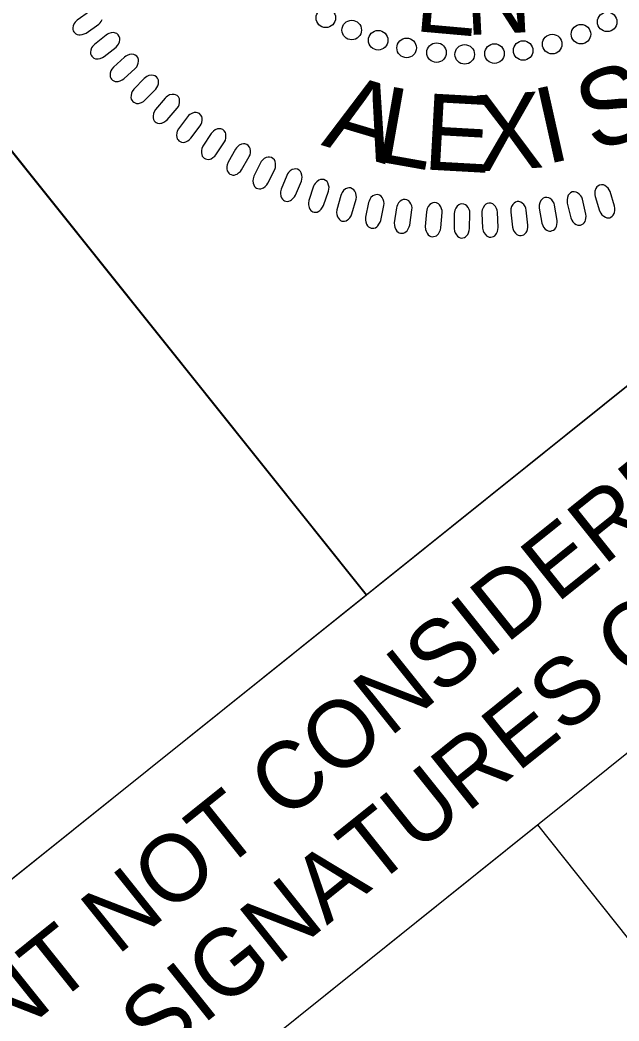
# Model space of a CAD drawing. Extents: x 472510 to 474509, y 505091 to 506998.
# Drawn here: x 473812.8 to 473861.9, y 506755.4 to 506837.4 of the extents above; entities that cross this region are included whole.
import ezdxf

# ---------------------------------------------------------------- set-up
doc = ezdxf.new("R2010")
doc.units = 0
for name, color, linetype in [('Sheet Clip Boundary CELL', 7, 'Continuous'), ('Sheet PE Seal Cell', 7, 'Continuous'), ('Sheet Plan CELL', 7, 'Continuous'), ('Sheet Sticker Exception Certification CELL', 7, 'Continuous'), ('Sheet Sticker Incomplete CELL', 7, 'Continuous')]:
    doc.layers.add(name, color=color, linetype=linetype)

msp = doc.modelspace()

# ---------------------------------------------------------------- linework, layer by layer
at = {"layer": 'Sheet Clip Boundary CELL'}
msp.add_lwpolyline([(473777.72, 506709.447), (473669.277, 506844.945), (472855.074, 506193.317), (472968.618, 506051.104), (472829.891, 505940.077), (472768.979, 505889.401), (473229.883, 505313.507), (473287.266, 505310.531), (473108.816, 505533.501), (473372.025, 505744.154), (473550.474, 505521.184), (474139.22, 505988.542), (474128.73, 506014.502), (474324.313, 506183.285), (473855.207, 506771.462)], close=True, dxfattribs=at)
at = {"layer": 'Sheet PE Seal Cell'}
msp.add_lwpolyline([(473818.447, 506838.07), (473817.443, 506837.365), (473817.284, 506837.208), (473817.2, 506837.085), (473817.125, 506836.896), (473817.091, 506836.753), (473817.091, 506836.616), (473817.118, 506836.507), (473817.166, 506836.404), (473817.247, 506836.324), (473817.341, 506836.243), (473817.449, 506836.192), (473817.591, 506836.163), (473817.691, 506836.16), (473817.852, 506836.191), (473818.033, 506836.245), (473818.177, 506836.318), (473819.21, 506837.034), (473819.336, 506837.15), (473819.424, 506837.267), (473819.503, 506837.432)], dxfattribs=at)
for points in [[(473819.814, 506836.153), (473818.856, 506835.386), (473818.709, 506835.22), (473818.632, 506835.092), (473818.569, 506834.899), (473818.544, 506834.754), (473818.553, 506834.617), (473818.587, 506834.511), (473818.641, 506834.41), (473818.727, 506834.336), (473818.825, 506834.261), (473818.936, 506834.216), (473819.08, 506834.197), (473819.18, 506834.2), (473819.339, 506834.241), (473819.516, 506834.306), (473819.655, 506834.388), (473820.641, 506835.168), (473820.759, 506835.29), (473820.84, 506835.413), (473820.908, 506835.583), (473820.948, 506835.757), (473820.949, 506835.883), (473820.898, 506836.043), (473820.82, 506836.173), (473820.695, 506836.264), (473820.591, 506836.314), (473820.434, 506836.352), (473820.227, 506836.339), (473820.045, 506836.28), (473819.925, 506836.222)], [(473821.329, 506834.345), (473820.42, 506833.52), (473820.283, 506833.345), (473820.215, 506833.212), (473820.165, 506833.015), (473820.148, 506832.869), (473820.165, 506832.733), (473820.206, 506832.629), (473820.267, 506832.532), (473820.357, 506832.463), (473820.46, 506832.395), (473820.574, 506832.357), (473820.718, 506832.347), (473820.818, 506832.356), (473820.973, 506832.407), (473821.147, 506832.483), (473821.279, 506832.574), (473822.215, 506833.413), (473822.325, 506833.544), (473822.398, 506833.671), (473822.456, 506833.845), (473822.484, 506834.022), (473822.478, 506834.147), (473822.417, 506834.304), (473822.331, 506834.428), (473822.201, 506834.512), (473822.093, 506834.556), (473821.934, 506834.582), (473821.729, 506834.557), (473821.55, 506834.486), (473821.434, 506834.421)], [(473822.945, 506832.589), (473822.09, 506831.709), (473821.965, 506831.525), (473821.904, 506831.389), (473821.867, 506831.189), (473821.86, 506831.042), (473821.885, 506830.907), (473821.933, 506830.806), (473821.999, 506830.713), (473822.093, 506830.649), (473822.2, 506830.587), (473822.317, 506830.557), (473822.462, 506830.556), (473822.56, 506830.572), (473822.712, 506830.632), (473822.88, 506830.719), (473823.007, 506830.818), (473823.888, 506831.715), (473823.99, 506831.852), (473824.055, 506831.984), (473824.102, 506832.16), (473824.119, 506832.338), (473824.105, 506832.463), (473824.034, 506832.616), (473823.94, 506832.734), (473823.805, 506832.81), (473823.695, 506832.847), (473823.535, 506832.864), (473823.331, 506832.825), (473823.158, 506832.743), (473823.046, 506832.671)], [(473824.658, 506830.981), (473823.861, 506830.049), (473823.746, 506829.858), (473823.695, 506829.719), (473823.67, 506829.516), (473823.673, 506829.37), (473823.706, 506829.236), (473823.76, 506829.138), (473823.832, 506829.05), (473823.93, 506828.993), (473824.04, 506828.938), (473824.159, 506828.915), (473824.303, 506828.923), (473824.4, 506828.944), (473824.549, 506829.014), (473824.711, 506829.112), (473824.832, 506829.218), (473825.654, 506830.168), (473825.747, 506830.312), (473825.804, 506830.447), (473825.84, 506830.626), (473825.845, 506830.806), (473825.823, 506830.929), (473825.743, 506831.077), (473825.642, 506831.19), (473825.503, 506831.256), (473825.391, 506831.287), (473825.23, 506831.293), (473825.029, 506831.242), (473824.86, 506831.149), (473824.754, 506831.07)], [(473826.495, 506829.453), (473825.758, 506828.473), (473825.656, 506828.275), (473825.613, 506828.132), (473825.601, 506827.929), (473825.613, 506827.783), (473825.655, 506827.652), (473825.715, 506827.557), (473825.792, 506827.474), (473825.894, 506827.423), (473826.007, 506827.375), (473826.127, 506827.359), (473826.271, 506827.376), (473826.367, 506827.404), (473826.51, 506827.483), (473826.666, 506827.591), (473826.779, 506827.705), (473827.541, 506828.704), (473827.625, 506828.853), (473827.673, 506828.992), (473827.697, 506829.173), (473827.691, 506829.352), (473827.662, 506829.474), (473827.572, 506829.617), (473827.464, 506829.723), (473827.321, 506829.78), (473827.207, 506829.803), (473827.046, 506829.801), (473826.849, 506829.736), (473826.687, 506829.634), (473826.585, 506829.548)], [(473828.433, 506828.079), (473827.759, 506827.054), (473827.669, 506826.85), (473827.635, 506826.705), (473827.636, 506826.501), (473827.658, 506826.356), (473827.707, 506826.228), (473827.773, 506826.137), (473827.855, 506826.059), (473827.96, 506826.015), (473828.076, 506825.974), (473828.196, 506825.966), (473828.339, 506825.992), (473828.433, 506826.025), (473828.571, 506826.113), (473828.72, 506826.231), (473828.826, 506826.351), (473829.523, 506827.397), (473829.597, 506827.551), (473829.637, 506827.692), (473829.649, 506827.875), (473829.633, 506828.053), (473829.596, 506828.173), (473829.497, 506828.309), (473829.383, 506828.408), (473829.236, 506828.457), (473829.122, 506828.473), (473828.961, 506828.46), (473828.768, 506828.384), (473828.613, 506828.271), (473828.517, 506828.179)], [(473830.423, 506826.806), (473829.814, 506825.741), (473829.738, 506825.532), (473829.714, 506825.385), (473829.727, 506825.182), (473829.757, 506825.038), (473829.815, 506824.913), (473829.886, 506824.827), (473829.973, 506824.754), (473830.08, 506824.716), (473830.199, 506824.683), (473830.319, 506824.682), (473830.46, 506824.717), (473830.552, 506824.757), (473830.685, 506824.853), (473830.825, 506824.98), (473830.924, 506825.107), (473831.554, 506826.194), (473831.619, 506826.353), (473831.649, 506826.496), (473831.65, 506826.679), (473831.622, 506826.856), (473831.578, 506826.973), (473831.471, 506827.103), (473831.351, 506827.195), (473831.202, 506827.234), (473831.086, 506827.243), (473830.926, 506827.22), (473830.738, 506827.131), (473830.59, 506827.009), (473830.501, 506826.911)], [(473832.475, 506825.683), (473831.934, 506824.581), (473831.871, 506824.368), (473831.856, 506824.219), (473831.883, 506824.018), (473831.921, 506823.876), (473831.987, 506823.755), (473832.063, 506823.673), (473832.155, 506823.606), (473832.264, 506823.575), (473832.385, 506823.549), (473832.505, 506823.556), (473832.643, 506823.6), (473832.732, 506823.645), (473832.859, 506823.75), (473832.991, 506823.885), (473833.082, 506824.018), (473833.643, 506825.142), (473833.697, 506825.305), (473833.718, 506825.45), (473833.708, 506825.632), (473833.669, 506825.807), (473833.617, 506825.922), (473833.502, 506826.045), (473833.376, 506826.129), (473833.225, 506826.158), (473833.109, 506826.16), (473832.951, 506826.127), (473832.77, 506826.027), (473832.629, 506825.895), (473832.545, 506825.792)], [(473834.635, 506824.659), (473834.165, 506823.526), (473834.115, 506823.31), (473834.11, 506823.16), (473834.148, 506822.961), (473834.196, 506822.822), (473834.269, 506822.706), (473834.35, 506822.628), (473834.447, 506822.567), (473834.557, 506822.543), (473834.68, 506822.525), (473834.799, 506822.539), (473834.934, 506822.592), (473835.02, 506822.642), (473835.139, 506822.755), (473835.263, 506822.898), (473835.346, 506823.036), (473835.834, 506824.194), (473835.878, 506824.359), (473835.89, 506824.505), (473835.868, 506824.687), (473835.819, 506824.858), (473835.76, 506824.97), (473835.637, 506825.085), (473835.507, 506825.161), (473835.353, 506825.181), (473835.238, 506825.176), (473835.082, 506825.132), (473834.907, 506825.021), (473834.776, 506824.881), (473834.699, 506824.773)], [(473836.834, 506823.762), (473836.436, 506822.601), (473836.4, 506822.382), (473836.404, 506822.233), (473836.455, 506822.036), (473836.511, 506821.901), (473836.592, 506821.789), (473836.678, 506821.717), (473836.777, 506821.662), (473836.89, 506821.645), (473837.013, 506821.634), (473837.131, 506821.656), (473837.262, 506821.717), (473837.345, 506821.773), (473837.457, 506821.893), (473837.572, 506822.043), (473837.645, 506822.186), (473838.06, 506823.373), (473838.094, 506823.54), (473838.096, 506823.687), (473838.064, 506823.867), (473838.003, 506824.035), (473837.937, 506824.143), (473837.808, 506824.25), (473837.673, 506824.317), (473837.519, 506824.328), (473837.404, 506824.315), (473837.251, 506824.262), (473837.083, 506824.14), (473836.96, 506823.992), (473836.891, 506823.879)], [(473839.065, 506823.018), (473838.74, 506821.834), (473838.718, 506821.613), (473838.731, 506821.464), (473838.795, 506821.271), (473838.86, 506821.14), (473838.947, 506821.033), (473839.037, 506820.967), (473839.14, 506820.918), (473839.253, 506820.908), (473839.377, 506820.905), (473839.494, 506820.935), (473839.621, 506821.004), (473839.699, 506821.065), (473839.804, 506821.191), (473839.909, 506821.348), (473839.973, 506821.496), (473840.313, 506822.706), (473840.336, 506822.875), (473840.329, 506823.022), (473840.285, 506823.199), (473840.214, 506823.363), (473840.142, 506823.467), (473840.006, 506823.566), (473839.867, 506823.625), (473839.712, 506823.625), (473839.598, 506823.605), (473839.449, 506823.543), (473839.289, 506823.411), (473839.177, 506823.255), (473839.114, 506823.139)], [(473859.922, 506822.926), (473860.282, 506821.753), (473860.382, 506821.554), (473860.472, 506821.436), (473860.63, 506821.306), (473860.755, 506821.23), (473860.886, 506821.187), (473860.997, 506821.179), (473861.111, 506821.193), (473861.211, 506821.245), (473861.317, 506821.309), (473861.4, 506821.396), (473861.47, 506821.523), (473861.504, 506821.616), (473861.524, 506821.779), (473861.529, 506821.968), (473861.504, 506822.128), (473861.142, 506823.331), (473861.072, 506823.487), (473860.987, 506823.606), (473860.855, 506823.733), (473860.707, 506823.834), (473860.59, 506823.881), (473860.423, 506823.893), (473860.273, 506823.868), (473860.143, 506823.786), (473860.058, 506823.707), (473859.965, 506823.575), (473859.901, 506823.378), (473859.889, 506823.186), (473859.899, 506823.054)], [(473841.337, 506822.426), (473841.087, 506821.224), (473841.079, 506821.003), (473841.101, 506820.855), (473841.176, 506820.666), (473841.249, 506820.539), (473841.343, 506820.438), (473841.437, 506820.378), (473841.543, 506820.335), (473841.656, 506820.332), (473841.78, 506820.337), (473841.894, 506820.374), (473842.017, 506820.451), (473842.092, 506820.517), (473842.189, 506820.65), (473842.283, 506820.813), (473842.338, 506820.964), (473842.601, 506822.194), (473842.614, 506822.364), (473842.598, 506822.51), (473842.543, 506822.684), (473842.462, 506822.844), (473842.383, 506822.942), (473842.241, 506823.032), (473842.099, 506823.082), (473841.945, 506823.073), (473841.832, 506823.046), (473841.687, 506822.974), (473841.535, 506822.833), (473841.432, 506822.67), (473841.377, 506822.549)], [(473843.622, 506821.987), (473843.448, 506820.772), (473843.454, 506820.55), (473843.485, 506820.405), (473843.572, 506820.22), (473843.653, 506820.098), (473843.753, 506820.003), (473843.851, 506819.949), (473843.959, 506819.914), (473844.073, 506819.918), (473844.196, 506819.93), (473844.307, 506819.974), (473844.425, 506820.059), (473844.496, 506820.129), (473844.584, 506820.268), (473844.668, 506820.437), (473844.713, 506820.591), (473844.899, 506821.834), (473844.901, 506822.005), (473844.875, 506822.15), (473844.81, 506822.32), (473844.719, 506822.475), (473844.634, 506822.567), (473844.487, 506822.649), (473844.341, 506822.69), (473844.188, 506822.671), (473844.077, 506822.637), (473843.937, 506822.556), (473843.795, 506822.405), (473843.703, 506822.237), (473843.655, 506822.113)], [(473852.997, 506821.649), (473853.131, 506820.429), (473853.191, 506820.215), (473853.258, 506820.082), (473853.388, 506819.925), (473853.497, 506819.827), (473853.617, 506819.76), (473853.725, 506819.731), (473853.839, 506819.724), (473853.948, 506819.756), (473854.064, 506819.798), (473854.161, 506819.87), (473854.255, 506819.98), (473854.306, 506820.066), (473854.356, 506820.222), (473854.396, 506820.407), (473854.401, 506820.568), (473854.271, 506821.818), (473854.23, 506821.984), (473854.171, 506822.118), (473854.064, 506822.267), (473853.938, 506822.394), (473853.832, 506822.462), (473853.67, 506822.505), (473853.519, 506822.508), (473853.375, 506822.452), (473853.276, 506822.391), (473853.16, 506822.279), (473853.06, 506822.097), (473853.013, 506821.911), (473852.997, 506821.779)], [(473855.332, 506821.96), (473855.542, 506820.752), (473855.616, 506820.542), (473855.691, 506820.413), (473855.831, 506820.265), (473855.945, 506820.174), (473856.07, 506820.114), (473856.179, 506820.093), (473856.294, 506820.093), (473856.4, 506820.132), (473856.513, 506820.181), (473856.606, 506820.258), (473856.692, 506820.375), (473856.737, 506820.463), (473856.778, 506820.622), (473856.806, 506820.809), (473856.801, 506820.97), (473856.593, 506822.21), (473856.542, 506822.373), (473856.473, 506822.503), (473856.358, 506822.645), (473856.224, 506822.763), (473856.115, 506822.825), (473855.95, 506822.857), (473855.799, 506822.851), (473855.659, 506822.786), (473855.564, 506822.719), (473855.456, 506822.599), (473855.367, 506822.412), (473855.331, 506822.223), (473855.324, 506822.091)], [(473857.631, 506822.383), (473857.916, 506821.191), (473858.004, 506820.986), (473858.087, 506820.862), (473858.236, 506820.723), (473858.356, 506820.639), (473858.483, 506820.588), (473858.594, 506820.573), (473858.708, 506820.58), (473858.812, 506820.626), (473858.922, 506820.682), (473859.009, 506820.765), (473859.088, 506820.886), (473859.128, 506820.978), (473859.159, 506821.139), (473859.175, 506821.327), (473859.16, 506821.488), (473858.875, 506822.712), (473858.813, 506822.872), (473858.737, 506822.996), (473858.613, 506823.131), (473858.471, 506823.241), (473858.358, 506823.296), (473858.192, 506823.317), (473858.041, 506823.302), (473857.905, 506823.229), (473857.815, 506823.155), (473857.715, 506823.029), (473857.638, 506822.837), (473857.615, 506822.646), (473857.616, 506822.513)], [(473846.088, 506821.683), (473845.991, 506820.46), (473846.01, 506820.238), (473846.051, 506820.095), (473846.15, 506819.917), (473846.238, 506819.799), (473846.343, 506819.711), (473846.444, 506819.664), (473846.555, 506819.635), (473846.668, 506819.646), (473846.79, 506819.666), (473846.899, 506819.717), (473847.011, 506819.809), (473847.077, 506819.883), (473847.156, 506820.027), (473847.229, 506820.201), (473847.265, 506820.359), (473847.372, 506821.611), (473847.363, 506821.781), (473847.329, 506821.924), (473847.252, 506822.09), (473847.152, 506822.238), (473847.061, 506822.325), (473846.91, 506822.398), (473846.761, 506822.43), (473846.61, 506822.401), (473846.501, 506822.36), (473846.367, 506822.271), (473846.234, 506822.111), (473846.153, 506821.937), (473846.113, 506821.811)], [(473848.363, 506821.544), (473848.343, 506820.317), (473848.377, 506820.097), (473848.426, 506819.957), (473848.536, 506819.786), (473848.632, 506819.674), (473848.742, 506819.593), (473848.846, 506819.551), (473848.958, 506819.529), (473849.07, 506819.547), (473849.19, 506819.575), (473849.296, 506819.633), (473849.402, 506819.732), (473849.464, 506819.81), (473849.533, 506819.959), (473849.596, 506820.137), (473849.621, 506820.296), (473849.649, 506821.553), (473849.63, 506821.723), (473849.586, 506821.863), (473849.5, 506822.024), (473849.391, 506822.165), (473849.294, 506822.247), (473849.138, 506822.309), (473848.989, 506822.331), (473848.839, 506822.294), (473848.733, 506822.245), (473848.605, 506822.148), (473848.483, 506821.981), (473848.412, 506821.802), (473848.38, 506821.673)], [(473850.629, 506821.564), (473850.686, 506820.338), (473850.733, 506820.121), (473850.792, 506819.983), (473850.912, 506819.819), (473851.015, 506819.714), (473851.13, 506819.64), (473851.236, 506819.604), (473851.349, 506819.59), (473851.46, 506819.615), (473851.578, 506819.651), (473851.68, 506819.715), (473851.78, 506819.82), (473851.836, 506819.902), (473851.896, 506820.055), (473851.948, 506820.237), (473851.963, 506820.397), (473851.912, 506821.652), (473851.882, 506821.821), (473851.83, 506821.958), (473851.734, 506822.113), (473851.616, 506822.248), (473851.515, 506822.323), (473851.355, 506822.376), (473851.204, 506822.389), (473851.057, 506822.342), (473850.955, 506822.287), (473850.832, 506822.182), (473850.721, 506822.007), (473850.662, 506821.824), (473850.638, 506821.693)]]:
    msp.add_lwpolyline(points, close=True, dxfattribs=at)
for centre in [(473837.831, 506837.562), (473839.958, 506836.56), (473860.905, 506837.229), (473842.123, 506835.726), (473858.753, 506836.223), (473844.461, 506835.097), (473854.014, 506834.881), (473856.396, 506835.409), (473846.912, 506834.71), (473849.219, 506834.566), (473851.663, 506834.633)]:
    msp.add_circle(centre, 0.801, dxfattribs=at)
at = {"layer": 'Sheet Plan CELL'}
msp.add_line((473770.852, 506878.127), (473841.134, 506790.33), dxfattribs=at)
for points in [[(473770.852, 506878.127), (473848.909, 506940.614), (473919.222, 506852.778), (473841.155, 506790.284)], [(473692.738, 506815.611), (473770.852, 506878.127), (473841.155, 506790.284), (473763.036, 506727.795)]]:
    msp.add_lwpolyline(points, close=True, dxfattribs=at)
at = {"layer": 'Sheet Sticker Exception Certification CELL'}
for p, q in [((473763.036, 506727.795), (473919.214, 506852.788)), ((473763.036, 506727.795), (473919.214, 506852.788)), ((473933.898, 506834.441), (473777.72, 506709.447)), ((473933.898, 506834.441), (473777.72, 506709.447))]:
    msp.add_line(p, q, dxfattribs=at)

# ---------------------------------------------------------------- texts
at = {"layer": 'Sheet PE Seal Cell'}
for s, height, rotation, p in [('E', 5.669, 354.93681, (473845.044, 506836.483)), ('N', 5.669, 2.87661, (473849.339, 506836.134)), ('S', 6.236, 19.45864, (473859.765, 506826.503)), ('A', 6.236, 343.35467, (473837.393, 506827.155)), ('L', 6.236, 349.97435, (473841.676, 506825.869)), ('I', 6.236, 12.61298, (473855.853, 506825.541)), ('E', 6.236, 356.82, (473845.72, 506825.158)), ('X', 6.236, 3.66566, (473850.233, 506824.963))]:
    msp.add_text(s, height=height, rotation=rotation, dxfattribs=at).set_placement(p)
at = {"layer": 'Sheet Sticker Exception Certification CELL'}
for s, p in [('DOCUMENT NOT CONSIDERED FINAL', (473785.951, 506732.884)), ('DOCUMENT NOT CONSIDERED FINAL', (473785.951, 506732.884)), ('UNLESS ALL SIGNATURES COMPLETED', (473787.491, 506722.844)), ('UNLESS ALL SIGNATURES COMPLETED', (473787.491, 506722.844))]:
    msp.add_text(s, height=5.5, rotation=38.67122, dxfattribs=at).set_placement(p)
at = {"layer": 'Sheet Sticker Incomplete CELL'}
for s, height, p in [('INCOMPLETE PLANS', 11.52, (473748.292, 506803.011)), ('DO NOT USE FOR R/W ACQUISITION', 5.76, (473755.172, 506799.615))]:
    msp.add_text(s, height=height, rotation=38.67122, dxfattribs=at).set_placement(p)

doc.saveas('drawing.dxf')
